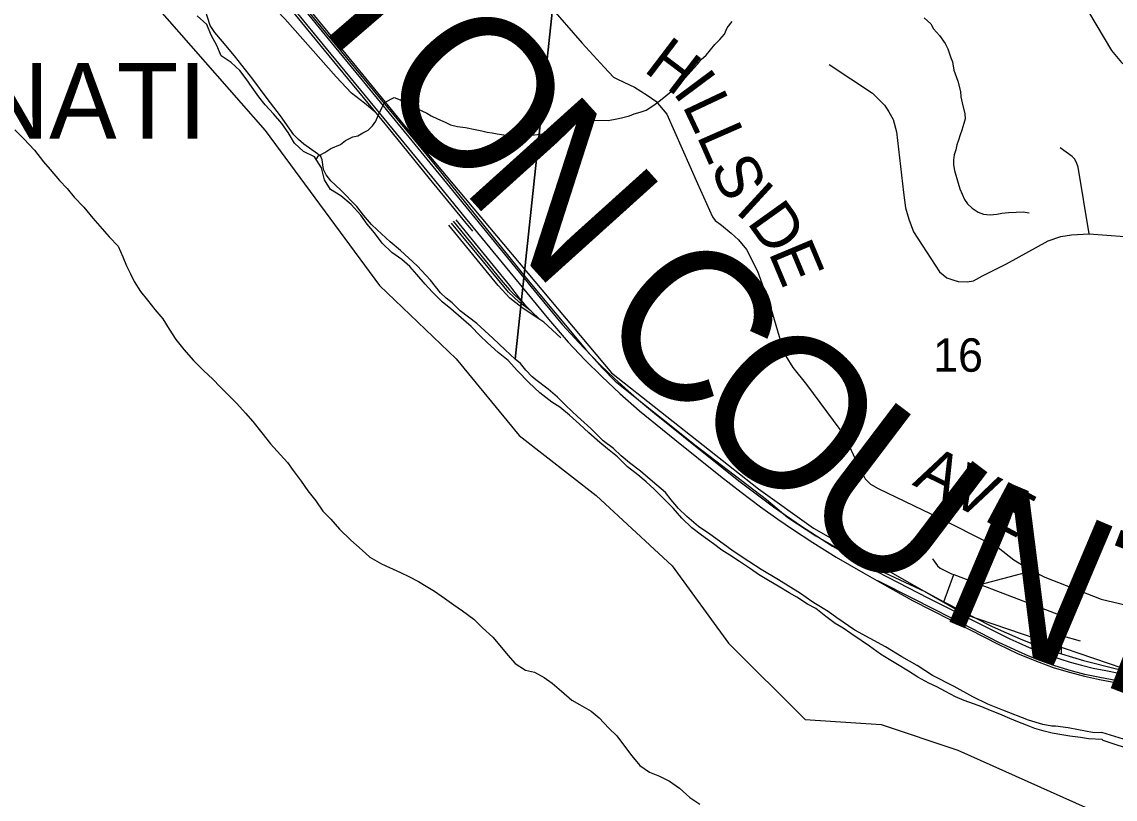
# Model space of a CAD drawing. Extents: x 0 to 34, y -2 to 22.
# Drawn here: x 3.329 to 4.698, y 14.734 to 15.708 of the extents above; entities that cross this region are included whole.
import ezdxf

# ---------------------------------------------------------------- set-up
doc = ezdxf.new("R2010")
doc.units = 0
for name, color, linetype in [('GM_X_City_Street', 7, 'Continuous'), ('GM_X_Corporation_Text', 7, 'Continuous'), ('GM_X_County_Road', 7, 'Continuous'), ('GM_X_County_Road_Text', 7, 'Continuous'), ('GM_X_County_Text', 7, 'Continuous'), ('GM_X_Major_River', 7, 'Continuous'), ('GM_X_Minor_River', 7, 'Continuous'), ('GM_X_Rail_Line', 7, 'Continuous'), ('GM_X_Section', 7, 'Continuous'), ('GM_X_Section_Text', 7, 'Continuous'), ('GM_X_Township_Road', 7, 'Continuous'), ('GM_X_US_Route', 7, 'Continuous'), ('SH_Cut_Line', 7, 'Continuous')]:
    doc.layers.add(name, color=color, linetype=linetype)

msp = doc.modelspace()

# ---------------------------------------------------------------- linework, layer by layer
at = {"layer": 'GM_X_City_Street'}
for p, q in [((4.483, 14.9817), (4.4955, 15.0156)), ((4.5286, 15.0031), (4.5932, 15.0205)), ((4.63, 14.9396), (4.6536, 14.9328))]:
    msp.add_line(p, q, dxfattribs=at)
for points in [[(4.4691, 15.0353), (4.4752, 15.0268), (4.4787, 15.0238), (4.4926, 15.0167), (4.4955, 15.0156), (4.5286, 15.0031), (4.63, 14.9646), (4.6322, 14.963), (4.634, 14.9604)], [(4.6303, 14.9166), (4.63, 14.9396), (4.634, 14.9604)]]:
    msp.add_lwpolyline(points, dxfattribs=at)
at = {"layer": 'GM_X_County_Road'}
msp.add_lwpolyline([(3.9883, 15.7297), (4.0304, 15.681), (4.0578, 15.6512), (4.0696, 15.6388), (4.0756, 15.6356), (4.0959, 15.6261), (4.112, 15.6162), (4.1228, 15.6084), (4.1365, 15.5922), (4.1748, 15.5053), (4.1936, 15.4635), (4.1969, 15.4589), (4.2047, 15.4531), (4.2171, 15.4433), (4.226, 15.4348), (4.2363, 15.4228), (4.2501, 15.3956), (4.2666, 15.3493), (4.2814, 15.2997), (4.2854, 15.2894), (4.2941, 15.2752), (4.3111, 15.2536), (4.3531, 15.1973), (4.3652, 15.1762), (4.3717, 15.1616), (4.3848, 15.1356), (4.3914, 15.129), (4.4008, 15.1235), (4.4781, 15.0865), (4.5404, 15.0552), (4.5513, 15.0497), (4.5707, 15.0341), (4.592, 15.0211), (4.5932, 15.0205), (4.6096, 15.0124), (4.6799, 14.9851), (4.7649, 14.9649)], dxfattribs=at)
at = {"layer": 'GM_X_Major_River'}
for points in [[(4.5759, 14.8313), (4.5657, 14.8353), (4.5533, 14.8408), (4.5416, 14.8455), (4.5307, 14.8499), (4.5201, 14.8538), (4.5084, 14.8582), (4.4979, 14.8625), (4.4851, 14.8692), (4.4742, 14.8751), (4.4644, 14.8798), (4.4504, 14.8872), (4.4388, 14.8946), (4.4253, 14.9032), (4.4148, 14.9094), (4.4039, 14.916), (4.39, 14.9261), (4.3795, 14.9331), (4.3667, 14.942), (4.357, 14.9486), (4.3472, 14.9545), (4.3356, 14.9634), (4.3228, 14.9731), (4.3127, 14.9786), (4.2991, 14.9875), (4.2894, 14.993), (4.2758, 15.0011), (4.2638, 15.0082), (4.251, 15.0156), (4.2413, 15.0229), (4.2274, 15.0319), (4.2154, 15.0401), (4.2052, 15.0463), (4.1947, 15.054), (4.1797, 15.0649), (4.1677, 15.0742), (4.155, 15.0862), (4.1442, 15.0989), (4.1338, 15.1093), (4.1207, 15.1228), (4.1106, 15.132), (4.1001, 15.1406), (4.0874, 15.1506), (4.0747, 15.1633), (4.0623, 15.173), (4.0526, 15.1812), (4.0387, 15.1931), (4.0271, 15.204), (4.0144, 15.2155), (4.0024, 15.2252), (3.9923, 15.2315), (3.9773, 15.2431), (3.9635, 15.2562), (3.9497, 15.2708), (3.9377, 15.2839), (3.9254, 15.294), (3.9119, 15.306), (3.9022, 15.3152), (3.8917, 15.3264), (3.879, 15.3372), (3.8659, 15.3485), (3.8554, 15.3574), (3.8427, 15.3697), (3.8338, 15.3793), (3.8237, 15.3913), (3.8148, 15.4016), (3.8047, 15.4102), (3.7923, 15.4191), (3.78, 15.4307), (3.7707, 15.4437), (3.7614, 15.4545), (3.7536, 15.4656), (3.7413, 15.4791), (3.7282, 15.4899), (3.7154, 15.4981), (3.708, 15.51), (3.7044, 15.5249), (3.6955, 15.5387), (3.6816, 15.5457), (3.6704, 15.5561), (3.6626, 15.5695), (3.6545, 15.5807), (3.644, 15.5926), (3.6336, 15.6038), (3.6258, 15.6138), (3.6176, 15.6257), (3.6098, 15.6364), (3.602, 15.6468), (3.5912, 15.6568), (3.5788, 15.6654), (3.5733, 15.6784), (3.5663, 15.6914), (3.5608, 15.7044), (3.5485, 15.7156)], [(3.3205, 15.5727), (3.3317, 15.5615), (3.3448, 15.5473), (3.3563, 15.5327), (3.3645, 15.5231), (3.3764, 15.5092), (3.3858, 15.4992), (3.3947, 15.4884), (3.4066, 15.4757), (3.4178, 15.4619), (3.4267, 15.4518), (3.4383, 15.4388), (3.4495, 15.4268), (3.4557, 15.4138), (3.4601, 15.4024), (3.4653, 15.3924), (3.4697, 15.3828), (3.4778, 15.3702), (3.4864, 15.3594), (3.4957, 15.3475), (3.5057, 15.336), (3.5135, 15.3229), (3.522, 15.3099), (3.5317, 15.2976), (3.544, 15.2837), (3.5567, 15.2714), (3.5683, 15.2602), (3.5772, 15.2506), (3.5873, 15.2406), (3.5981, 15.2301), (3.609, 15.2178), (3.6183, 15.2074), (3.6294, 15.1932), (3.6402, 15.1794), (3.6529, 15.1655), (3.6615, 15.1559), (3.6689, 15.1459), (3.6789, 15.1325), (3.6871, 15.1206), (3.6971, 15.1079), (3.706, 15.0952), (3.7157, 15.0852), (3.7269, 15.0725), (3.7411, 15.0586), (3.755, 15.0462), (3.7647, 15.0377), (3.7794, 15.0292), (3.7895, 15.0244), (3.8031, 15.0185), (3.8136, 15.0134), (3.8257, 15.0072), (3.8354, 15.0013), (3.8456, 14.9951), (3.8583, 14.9862), (3.87, 14.9776), (3.8805, 14.9703), (3.8947, 14.9598), (3.9059, 14.949), (3.9186, 14.9374), (3.9294, 14.9243), (3.9373, 14.9147), (3.9466, 14.9043), (3.9597, 14.8961), (3.9707, 14.8933), (3.9831, 14.8867), (3.9929, 14.8797), (4.0048, 14.8696), (4.0176, 14.8584), (4.0273, 14.853), (4.0416, 14.8448), (4.0517, 14.8362), (4.064, 14.8232)], [(4.064, 14.8232), (4.0738, 14.8139), (4.0845, 14.7993), (4.0927, 14.7889), (4.1028, 14.7766), (4.1148, 14.7681), (4.1272, 14.7633), (4.1396, 14.7571), (4.1524, 14.7482), (4.1651, 14.7366), (4.1779, 14.728)], [(4.6814, 14.8091), (4.6643, 14.8098), (4.6541, 14.8115), (4.6409, 14.8132), (4.631, 14.8149), (4.6189, 14.817), (4.6087, 14.8198), (4.597, 14.823), (4.5868, 14.827), (4.5759, 14.8313)], [(4.8856, 14.7322), (4.8702, 14.7379), (4.8597, 14.7427), (4.8484, 14.7471), (4.8386, 14.7519), (4.8285, 14.7556), (4.8112, 14.7621), (4.7961, 14.7663), (4.7864, 14.77), (4.7725, 14.7771), (4.7586, 14.7851), (4.7433, 14.7942), (4.7331, 14.7948), (4.7233, 14.7958), (4.7119, 14.7984), (4.695, 14.8037), (4.6826, 14.8079), (4.6814, 14.8091)]]:
    msp.add_lwpolyline(points, dxfattribs=at)
at = {"layer": 'GM_X_Minor_River'}
for points in [[(4.4586, 15.713), (4.4669, 15.7052)], [(3.6977, 15.5354), (3.7005, 15.5399), (3.7082, 15.5443), (3.7159, 15.5491), (3.7279, 15.5542), (3.7341, 15.5591), (3.7433, 15.5638), (3.7498, 15.5652), (3.756, 15.5689), (3.7626, 15.5722), (3.768, 15.5778), (3.7723, 15.5835), (3.7751, 15.5906), (3.7799, 15.6), (3.7831, 15.6068), (3.795, 15.6131), (3.8026, 15.6103), (3.8117, 15.6056), (3.8174, 15.6024), (3.8242, 15.5989), (3.8359, 15.5937), (3.8416, 15.5902), (3.8495, 15.5863), (3.859, 15.5823), (3.8658, 15.5787), (3.8745, 15.5767), (3.8845, 15.5754), (3.8966, 15.5732), (3.905, 15.5712), (3.9115, 15.5699), (3.9179, 15.5687), (3.924, 15.5678), (3.9297, 15.567), (3.9381, 15.5657), (3.9461, 15.5644), (3.9541, 15.5642), (3.9602, 15.5645), (3.9671, 15.5659), (3.9744, 15.5669), (3.9802, 15.5676), (3.9871, 15.5686), (3.9935, 15.5689), (3.9997, 15.5703), (4.0085, 15.572), (4.0155, 15.5764), (4.0235, 15.5805), (4.0305, 15.5838), (4.0377, 15.5844), (4.0442, 15.5847), (4.0629, 15.5843), (4.0737, 15.5864), (4.0798, 15.5878), (4.0898, 15.5903), (4.0956, 15.5925), (4.1032, 15.5946), (4.1105, 15.5972), (4.1202, 15.6035), (4.1287, 15.6098), (4.1419, 15.6206), (4.1477, 15.6273), (4.1563, 15.6344), (4.1664, 15.6456), (4.175, 15.6549), (4.1793, 15.6606), (4.1855, 15.6661), (4.1964, 15.6793), (4.2026, 15.6856), (4.2085, 15.6923), (4.2121, 15.7003), (4.2183, 15.7085)], [(4.4669, 15.7052), (4.4702, 15.6991), (4.4777, 15.6906), (4.4848, 15.6809), (4.4881, 15.674), (4.4913, 15.6641), (4.4939, 15.6576), (4.4956, 15.6473), (4.5007, 15.6335), (4.5039, 15.6205), (4.5046, 15.6141), (4.5059, 15.6064), (4.5095, 15.5927), (4.5098, 15.5866), (4.5081, 15.5806), (4.5057, 15.5722), (4.5037, 15.5662), (4.5013, 15.5598), (4.4993, 15.5537), (4.498, 15.5477), (4.496, 15.5412), (4.4951, 15.5348), (4.4954, 15.5287), (4.4964, 15.5219), (4.5011, 15.5058), (4.5032, 15.4986), (4.5091, 15.4855), (4.5128, 15.4798), (4.5184, 15.4747), (4.526, 15.4696), (4.5328, 15.4669), (4.5412, 15.4663), (4.5496, 15.4669), (4.5557, 15.4683), (4.5642, 15.469), (4.5737, 15.4695), (4.5825, 15.4701), (4.5901, 15.4685)]]:
    msp.add_lwpolyline(points, dxfattribs=at)
at = {"layer": 'GM_X_Rail_Line'}
msp.add_line((3.9662, 15.3459), (3.9773, 15.3351), dxfattribs=at)
for points in [[(3.2132, 16.1958), (3.4289, 16.0129), (3.5157, 15.9354), (3.8272, 15.5543), (4.0672, 15.2682), (4.251, 15.1231), (4.3199, 15.0739), (4.5092, 14.9662), (4.7242, 14.8927), (4.942, 14.8608), (5.225, 14.8332), (5.6876, 14.8174), (5.8521, 14.8361), (5.9916, 14.8618), (6.1483, 14.9087), (6.6423, 15.1295), (6.8334, 15.1788), (6.9496, 15.2223), (7.5162, 15.4575), (7.5472, 15.4815), (7.5981, 15.5082), (7.6394, 15.5247), (7.6638, 15.5316), (7.8133, 15.5592)], [(3.297, 15.9555), (3.6339, 15.5717), (3.7768, 15.3776), (3.8729, 15.2858), (3.9515, 15.1899), (4.048, 15.1148), (4.143, 15.0265), (4.2137, 14.9298), (4.3094, 14.8343), (4.4047, 14.8279), (4.5005, 14.7957), (4.6757, 14.7172)], [(3.7711, 15.595), (3.7579, 15.6061), (3.7418, 15.6187), (3.7227, 15.6392), (3.6585, 15.7115), (3.6187, 15.7534), (3.5891, 15.7876), (3.5432, 15.8424), (3.5011, 15.8943)], [(3.5604, 15.8517), (3.585, 15.8223), (3.5887, 15.8179), (3.7074, 15.6726), (3.7854, 15.5776), (3.8391, 15.5119), (3.8813, 15.4603), (3.8932, 15.4459)], [(3.5913, 15.82), (3.71, 15.6747), (3.7881, 15.5797), (3.8417, 15.514), (3.884, 15.4624), (3.9399, 15.3945), (3.9884, 15.3355), (4.0129, 15.3067), (4.0336, 15.2846), (4.0549, 15.2636), (4.0777, 15.2425), (4.1023, 15.2209), (4.1466, 15.1849), (4.2037, 15.1389), (4.2293, 15.1187), (4.2538, 15.1005), (4.2753, 15.0851), (4.2939, 15.0725), (4.319, 15.0559), (4.3483, 15.0376), (4.3818, 15.0182), (4.4052, 15.0051), (4.444, 14.9833), (4.5163, 14.9463), (4.5511, 14.9285), (4.5754, 14.917), (4.5885, 14.9114), (4.6025, 14.906), (4.62, 14.8995), (4.6387, 14.8937), (4.659, 14.8883), (4.6778, 14.8842), (4.7114, 14.8781)], [(3.6189, 15.8012), (3.7201, 15.6774), (3.753, 15.6375), (3.868, 15.4968), (3.974, 15.3669), (4.006, 15.3284), (4.0262, 15.3062), (4.0416, 15.2899), (4.0537, 15.2777), (4.0704, 15.2617), (4.0846, 15.2489), (4.0985, 15.2366), (4.1212, 15.2177), (4.1763, 15.1732), (4.2282, 15.1317), (4.2699, 15.1005), (4.3038, 15.0772), (4.3439, 15.0513), (4.3584, 15.0428), (4.3882, 15.0254), (4.4633, 14.9864), (4.5657, 14.9352), (4.5768, 14.9301), (4.5901, 14.9242), (4.6092, 14.9167), (4.6282, 14.9102), (4.6413, 14.906), (4.6556, 14.9022), (4.6702, 14.8985), (4.6857, 14.8954), (4.702, 14.8923)], [(3.9773, 15.3351), (3.9693, 15.3405), (3.9551, 15.35), (3.9398, 15.3619), (3.9253, 15.3776), (3.8637, 15.4534)], [(3.9662, 15.3459), (3.9514, 15.3569), (3.9383, 15.3694), (3.8934, 15.4239), (3.8669, 15.4559)], [(3.869, 15.4581), (3.9292, 15.3843), (3.9395, 15.3723), (3.9589, 15.3537)], [(3.8723, 15.4601), (3.9395, 15.3779), (3.9518, 15.3617), (3.9589, 15.3537)], [(3.9589, 15.3537), (3.9627, 15.3494), (3.9662, 15.3459)], [(4.0038, 15.3122), (3.9823, 15.3317), (3.9773, 15.3351)], [(4.7118, 14.8804), (4.6782, 14.8866), (4.6595, 14.8907), (4.6394, 14.896), (4.6208, 14.9018), (4.6033, 14.9082), (4.5895, 14.9137), (4.5764, 14.9192), (4.5521, 14.9307), (4.5174, 14.9484), (4.4451, 14.9855), (4.4004, 15.0077)]]:
    msp.add_lwpolyline(points, dxfattribs=at)
at = {"layer": 'GM_X_Section'}
for points in [[(4.012, 15.9002), (3.9466, 15.2855), (3.934, 15.2971), (3.9185, 15.3119), (3.8985, 15.3302), (3.8776, 15.3458), (3.8677, 15.3559), (3.8602, 15.3618), (3.8532, 15.3684), (3.8407, 15.3843), (3.8241, 15.4025), (3.803, 15.4215), (3.79, 15.4325), (3.7737, 15.4473), (3.7666, 15.4542), (3.7567, 15.4658), (3.7486, 15.4766), (3.7279, 15.4976), (3.7157, 15.5089), (3.7102, 15.5162), (3.7069, 15.5231), (3.7049, 15.5349), (3.7032, 15.5391), (3.6994, 15.5426), (3.6819, 15.5548), (3.6753, 15.5606), (3.6697, 15.5665), (3.6529, 15.59), (3.6363, 15.612), (3.6184, 15.6359), (3.5952, 15.6652), (3.5801, 15.6834), (3.5705, 15.6946), (3.5647, 15.7035), (3.5591, 15.7218)], [(4.719, 14.8063), (4.681, 14.8178), (4.6808, 14.8176), (4.6691, 14.8179), (4.6518, 14.8213), (4.6386, 14.8239), (4.6231, 14.8258), (4.6182, 14.8259), (4.6072, 14.8281), (4.5892, 14.8334), (4.5569, 14.846), (4.5381, 14.8536), (4.5194, 14.8624), (4.4959, 14.8755), (4.4689, 14.8894), (4.4499, 14.902), (4.4305, 14.9127), (4.4103, 14.9253), (4.3718, 14.9459), (4.3494, 14.9616), (4.3383, 14.9695), (4.3226, 14.9789), (4.3181, 14.9821), (4.3036, 14.9919), (4.276, 15.0092), (4.2547, 15.0219), (4.239, 15.0321), (4.2193, 15.0451), (4.207, 15.0541), (4.1902, 15.0663), (4.1761, 15.0761), (4.1616, 15.0885), (4.1512, 15.0986), (4.142, 15.1095), (4.1347, 15.1184), (4.1187, 15.1324), (4.1035, 15.1453), (4.0897, 15.1558), (4.0793, 15.1644), (4.0697, 15.1737), (4.0567, 15.1831), (4.0415, 15.1987), (4.0245, 15.2135), (4.0104, 15.2271), (3.9997, 15.238), (3.9878, 15.2477), (3.9725, 15.2594), (3.9673, 15.2637), (3.9599, 15.2715), (3.9533, 15.28), (3.9466, 15.2855), (4.012, 15.9002)]]:
    msp.add_lwpolyline(points, dxfattribs=at)
at = {"layer": 'GM_X_Township_Road'}
for points in [[(4.6459, 15.7784), (4.644, 15.7655), (4.6458, 15.7571), (4.6484, 15.7489), (4.655, 15.7361), (4.6929, 15.6721), (4.7055, 15.6568), (4.7876, 15.5843), (4.8007, 15.5731), (4.8157, 15.5635), (4.8322, 15.553), (4.8491, 15.5416), (4.8598, 15.5358), (4.8854, 15.5263), (4.8943, 15.5258), (4.9038, 15.5244), (4.9155, 15.5249), (4.9249, 15.5271), (4.9347, 15.5301), (4.9577, 15.539), (4.9669, 15.5432), (4.976, 15.5486)], [(4.3396, 15.6545), (4.3938, 15.6186), (4.4088, 15.6034), (4.4115, 15.5996), (4.4144, 15.5951), (4.4196, 15.5854), (4.424, 15.5701), (4.4327, 15.494), (4.4353, 15.475), (4.4392, 15.4608), (4.4452, 15.445), (4.4779, 15.395), (4.4867, 15.3873), (4.4942, 15.3848), (4.5012, 15.3828), (4.5124, 15.3822), (4.5201, 15.3835), (4.5316, 15.3898), (4.5616, 15.4047), (4.6139, 15.4335), (4.6296, 15.4389), (4.6429, 15.4412), (4.665, 15.4423), (4.82, 15.4306)], [(4.665, 15.4423), (4.6512, 15.526), (4.6498, 15.5306), (4.6469, 15.536), (4.6439, 15.5391), (4.6286, 15.55)]]:
    msp.add_lwpolyline(points, dxfattribs=at)
at = {"layer": 'GM_X_US_Route'}
msp.add_line((4.1217, 15.218), (4.1296, 15.2116), dxfattribs=at)
for points in [[(3.1532, 16.2299), (3.1774, 16.2102), (3.1927, 16.1978), (3.2662, 16.1399), (3.3381, 16.0797), (3.4113, 16.0236), (3.454, 15.9871), (3.4937, 15.9512), (3.5323, 15.9084), (3.5719, 15.8607), (3.6379, 15.7814), (3.8444, 15.531), (3.9609, 15.3865), (4.0346, 15.2981), (4.0555, 15.2744), (4.0718, 15.2578), (4.1217, 15.218)], [(4.1296, 15.2116), (4.1731, 15.1769), (4.261, 15.1099), (4.288, 15.0871), (4.3229, 15.0642), (4.3745, 15.0345)], [(4.3745, 15.0345), (4.378, 15.0325), (4.3834, 15.03)], [(4.3834, 15.03), (4.4592, 14.9945), (4.483, 14.9817), (4.543, 14.9511), (4.5551, 14.9457)], [(4.5551, 14.9457), (4.5785, 14.9353), (4.6074, 14.9234), (4.6303, 14.9166), (4.6578, 14.9081), (4.6991, 14.8978), (4.7542, 14.889)]]:
    msp.add_lwpolyline(points, dxfattribs=at)
at = {"layer": 'SH_Cut_Line'}
msp.add_lwpolyline([(3.297, 15.9555), (3.6339, 15.5717), (3.7768, 15.3776), (3.8729, 15.2858), (3.9515, 15.1899), (4.048, 15.1148), (4.143, 15.0265), (4.2137, 14.9298), (4.3094, 14.8343), (4.4047, 14.8279), (4.5005, 14.7957), (4.6757, 14.7172)], dxfattribs=at)

# ---------------------------------------------------------------- texts
at = {"layer": 'GM_X_Corporation_Text'}
msp.add_text('CINCINNATI', height=0.0947, rotation=0, dxfattribs=at).set_placement((2.8357, 15.5616))
at = {"layer": 'GM_X_County_Road_Text'}
for s, rotation, p in [('H', 322.7635, (4.106, 15.6467)), ('I', 306.7122, (4.1429, 15.6194)), ('L', 295.2837, (4.1553, 15.6032)), ('L', 293.7034, (4.1733, 15.5652)), ('S', 293.5899, (4.1903, 15.5263)), ('I', 317.5313, (4.2206, 15.4702)), ('D', 305.5868, (4.2358, 15.4568)), ('E', 292.7395, (4.2632, 15.4191)), ('A', 333.7583, (4.4426, 15.1284)), ('V', 333.7058, (4.4874, 15.1063)), ('E', 331.9442, (4.5318, 15.0844))]:
    msp.add_text(s, height=0.0568, rotation=rotation, dxfattribs=at).set_placement(p)
at = {"layer": 'GM_X_County_Text'}
for s, rotation, p in [('T', 310.7744, (3.6706, 15.739)), ('O', 310.9226, (3.7635, 15.6313)), ('N', 312.0598, (3.8759, 15.5017)), ('C', 315.9774, (4.0379, 15.3258)), ('O', 318.4967, (4.1554, 15.2125)), ('U', 322.8562, (4.2931, 15.0915)), ('N', 337.1107, (4.471, 14.9647)), ('T', 338.7746, (4.6309, 14.8973))]:
    msp.add_text(s, height=0.1894, rotation=rotation, dxfattribs=at).set_placement(p)
at = {"layer": 'GM_X_Section_Text'}
msp.add_text('16', height=0.04186, rotation=0, dxfattribs=at).set_placement((4.4698, 15.2697))

doc.saveas('drawing.dxf')
